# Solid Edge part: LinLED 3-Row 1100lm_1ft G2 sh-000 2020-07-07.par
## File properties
Author: robert.pupel
Template: iso metric part.par
Last saved by: robert.pupel
Revision: 3
Application: Solid Edge
Gęstość: 0,000 kg/m^3
Dokładność: 0,990
Username: robert.pupel
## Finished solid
Body 1: solid body, 1388 faces, 3596 edges, 2286 vertices.
  Faces by surface: plane 876, cylinder 244, spline 160, cone 52, torus 22, sphere 20, spun 14
  Edges by curve: line 2486, curve on surface 564, circle 326, ellipse 132, spline 76, intersection 12
Bounding box of the edges (mm; curved faces can reach further): 280.000 x 5.050 x 55.000, from (-140, -5.05, -27.5) to (140, 0, 27.5).
Cylindrical faces by radius (mm): R0.2 x86, R0.2002 x4, R0.2169 x6, R0.25 x24, R0.3 x4, R0.3373 x6, R0.4 x16, R0.4006 x4, R0.4008 x4, R0.525 x4, R0.6 x24, R0.75 x8, R1 x14, R1.0894 x4, R1.1 x28, R2.375 x8
Conical faces (half-angle, radius in mm at the cone's reference point): 0.5 deg R0.5056 x8, 0.5 deg R1.0082 x8, 1 deg R0.5511 x4, 10 deg R0.2132 x4, 10 deg R0.4132 x4, 18.4844 deg R1.0657 x8, 27.363 deg R0.6214 x4, 45 deg R0.575 x4, 45 deg R0.625 x8
Toroidal faces (ring radius, tube radius in mm): R0.1 r0.2 x2, R0.8 r0.2 x8, R0.8522 r0.3 x4, R0.9002 r0.2 x2, R0.9018 r0.2 x2, R1.3 r0.2 x4
Spherical faces by radius (mm): R0.2 x16, R0.6 x4
Planar faces by outward normal: +x 94, +y 15, +z 101, -x 94, -y 138, -z 101, oblique 333
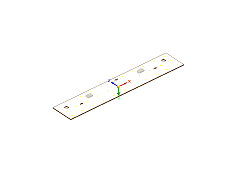
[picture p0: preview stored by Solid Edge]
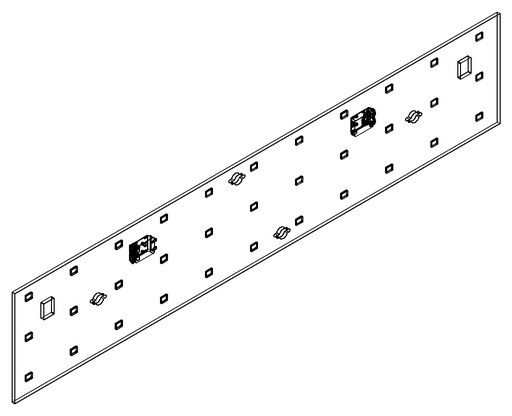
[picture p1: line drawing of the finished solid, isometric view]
